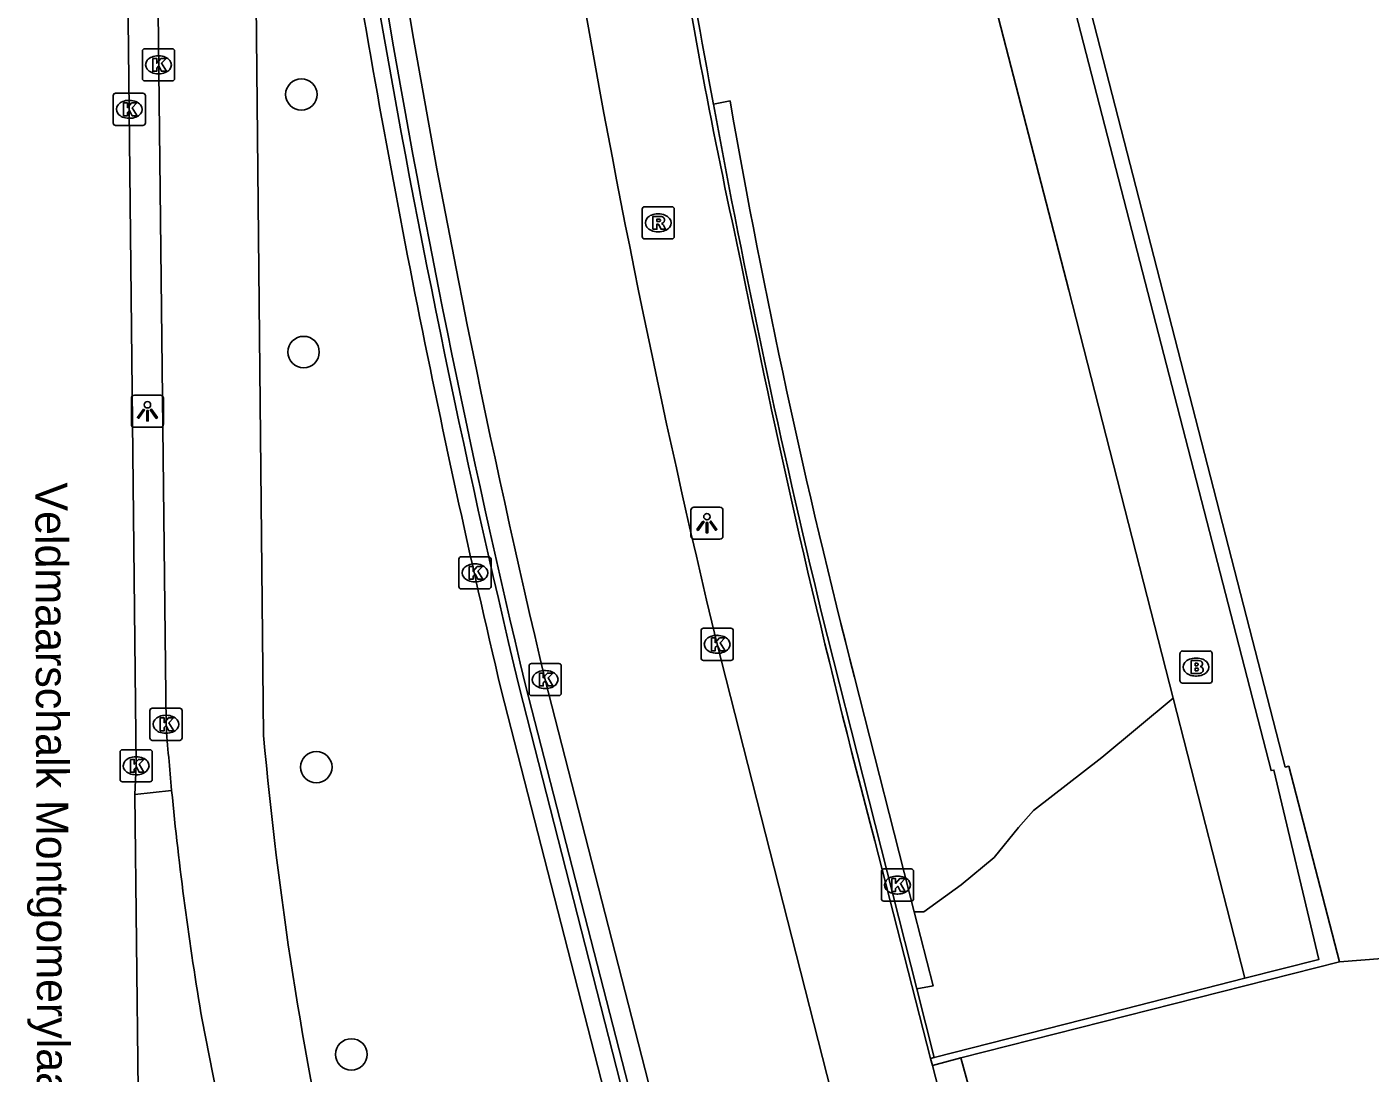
# Model space of a CAD drawing. Extents: x 160806 to 161707, y 383697 to 384148.
# Drawn here: x 161237.99 to 161279.79, y 383960.49 to 383993.06 of the extents above; entities that cross this region are included whole.
import ezdxf

# ---------------------------------------------------------------- set-up
doc = ezdxf.new("R2010")
doc.units = 0
for name, color, linetype in [('IMGEO_Boom', 7, 'Continuous'), ('IMGEO_Brandkraan', 7, 'Continuous'), ('IMGEO_Fietspad_open', 7, 'Continuous'), ('IMGEO_Groenvoorziening', 7, 'Continuous'), ('IMGEO_Kolk', 7, 'Continuous'), ('IMGEO_Lichtpunt', 7, 'Continuous'), ('IMGEO_Muur', 7, 'Continuous'), ('IMGEO_Openbare_ruimte_label', 7, 'Continuous'), ('IMGEO_Rijbaan_lokaal_gesloten', 7, 'Continuous'), ('IMGEO_Rioolput', 7, 'Continuous'), ('IMGEO_Verkeerseiland_gesloten', 7, 'Continuous'), ('IMGEO_Verkeerseiland_open', 7, 'Continuous'), ('IMGEO_Voetpad_gesloten', 7, 'Continuous'), ('IMGEO_Voetpad_open', 7, 'Continuous')]:
    doc.layers.add(name, color=color, linetype=linetype)

msp = doc.modelspace()

# ---------------------------------------------------------------- linework, layer by layer
at = {"layer": 'IMGEO_Boom'}
for centre in [(161246.528, 383990.956), (161246.596, 383982.939), (161246.992, 383970.018), (161248.083, 383961.076)]:
    msp.add_circle(centre, 0.489, dxfattribs=at)
at = {"layer": 'IMGEO_Brandkraan'}
for p, q in [((161273.87, 383972.707), (161273.87, 383973.559)), ((161273.945, 383973.633), (161274.797, 383973.633)), ((161274.358, 383973.413), (161274.383, 383973.413)), ((161274.871, 383973.559), (161274.871, 383972.707)), ((161274.797, 383972.633), (161273.945, 383972.633)), ((161274.381, 383972.853), (161274.356, 383972.853))]:
    msp.add_line(p, q, dxfattribs=at)
for points in [[(161273.87, 383972.707), (161273.87, 383973.559)], [(161273.945, 383973.633), (161274.797, 383973.633)], [(161274.218, 383973.333), (161274.218, 383972.933), (161274.431, 383972.933)], [(161274.449, 383973.333), (161274.218, 383973.333)], [(161274.871, 383973.559), (161274.871, 383972.707)], [(161274.397, 383973.252), (161274.343, 383973.252), (161274.343, 383973.176)], [(161274.343, 383973.176), (161274.396, 383973.176)], [(161274.405, 383973.1), (161274.343, 383973.1), (161274.343, 383973.019)], [(161274.343, 383973.019), (161274.405, 383973.019)], [(161274.797, 383972.633), (161273.945, 383972.633)]]:
    msp.add_lwpolyline(points, dxfattribs=at)
for centre, radius, start, end in [((161273.947, 383973.557), 0.0765, 91.552, 178.448), ((161273.947, 383973.557), 0.0765, 91.552, 178.448), ((161274.453, 383973.188), 0.145, 59.4692, 91.5367), ((161274.478, 383973.235), 0.0922, 285.5137, 58.1501), ((161274.795, 383973.557), 0.0765, 1.552, 88.448), ((161274.795, 383973.557), 0.0765, 1.552, 88.448), ((161274.398, 383973.214), 0.0379, 267.8285, 90.9355), ((161274.406, 383973.059), 0.0404, 269.8759, 90.5077), ((161274.437, 383973.184), 0.251, 268.6676, 293.5347), ((161274.483, 383973.043), 0.105, 301.3115, 78.989), ((161273.947, 383972.709), 0.0765, 181.552, 268.448), ((161273.947, 383972.709), 0.0765, 181.552, 268.448), ((161274.795, 383972.709), 0.0765, 271.552, 358.448), ((161274.795, 383972.709), 0.0765, 271.552, 358.448)]:
    msp.add_arc(centre, radius, start, end, dxfattribs=at)
for centre, major_axis, ratio, start_param, end_param in [((161274.357, 383973.133), (-0.387, 0.002), 0.722429, 4.712389, 7.853982), ((161274.382, 383973.133), (-0.39, 0.002), 0.717154, 1.570796, 4.712389)]:
    msp.add_ellipse(centre, major_axis=major_axis, ratio=ratio, start_param=start_param, end_param=end_param, dxfattribs=at)
at = {"layer": 'IMGEO_Fietspad_open'}
for points in [[(161241.737, 384044.23), (161241.861, 384012.393), (161241.998, 384000), (161242.316, 383971.348)], [(161245.354, 383970.999), (161245.058, 384000), (161244.731, 384032.028), (161244.792, 384040.216)], [(161266.435, 383946.5), (161265.897, 383948.588), (161264.804, 383952.922), (161259.465, 383973.845)], [(161261.187, 383945.139), (161260.855, 383946.434), (161254.116, 383972.74)], [(161246.739, 383948.007), (161244.797, 383955.231), (161243.442, 383962.149)]]:
    msp.add_lwpolyline(points, dxfattribs=at)
for centre, radius, start, end in [((161578.56, 384050.467), 328.165, 189.56836, 193.5024), ((161576.726, 384049.366), 331.586, 189.45347, 193.3612), ((161338.146, 383978.483), 96.095, 184.25791, 185.48645), ((161357.327, 383980.918), 112.412, 185.06229, 192.69832), ((161341.239, 383978.8), 99.205, 185.49822, 189.66271)]:
    msp.add_arc(centre, radius, start, end, dxfattribs=at)
at = {"layer": 'IMGEO_Groenvoorziening'}
msp.add_lwpolyline([(161273.656, 383972.166), (161271.438, 383970.317), (161269.309, 383968.667), (161268.844, 383968.144), (161268.086, 383967.207), (161267.06, 383966.359), (161265.9, 383965.512), (161265.599, 383965.509)], dxfattribs=at)
at = {"layer": 'IMGEO_Kolk'}
for p, q in [((161241.581, 383991.454), (161241.581, 383992.306)), ((161241.656, 383992.38), (161242.508, 383992.38)), ((161242.069, 383992.16), (161242.094, 383992.16)), ((161242.582, 383992.306), (161242.582, 383991.454)), ((161242.508, 383991.38), (161241.656, 383991.38)), ((161242.092, 383991.6), (161242.067, 383991.6)), ((161240.672, 383990.068), (161240.672, 383990.92)), ((161240.747, 383990.994), (161241.599, 383990.994)), ((161241.673, 383990.92), (161241.673, 383990.068)), ((161241.16, 383990.774), (161241.185, 383990.774)), ((161241.183, 383990.214), (161241.158, 383990.214)), ((161241.599, 383989.994), (161240.747, 383989.994)), ((161251.429, 383975.64), (161251.429, 383976.492)), ((161251.504, 383976.566), (161252.356, 383976.566)), ((161251.917, 383976.346), (161251.942, 383976.346)), ((161252.43, 383976.492), (161252.43, 383975.64)), ((161252.356, 383975.566), (161251.504, 383975.566)), ((161251.94, 383975.786), (161251.915, 383975.786)), ((161258.966, 383973.415), (161258.966, 383974.267)), ((161259.041, 383974.341), (161259.893, 383974.341)), ((161259.967, 383974.267), (161259.967, 383973.415)), ((161259.454, 383974.121), (161259.479, 383974.121)), ((161259.893, 383973.341), (161259.041, 383973.341)), ((161259.477, 383973.561), (161259.452, 383973.561)), ((161253.613, 383972.318), (161253.613, 383973.17)), ((161253.688, 383973.244), (161254.54, 383973.244)), ((161254.101, 383973.024), (161254.126, 383973.024)), ((161254.614, 383973.17), (161254.614, 383972.318)), ((161254.124, 383972.464), (161254.099, 383972.464)), ((161254.54, 383972.244), (161253.688, 383972.244)), ((161241.814, 383970.926), (161241.814, 383971.778)), ((161241.889, 383971.852), (161242.741, 383971.852)), ((161242.302, 383971.632), (161242.327, 383971.632)), ((161242.815, 383971.778), (161242.815, 383970.926)), ((161242.741, 383970.852), (161241.889, 383970.852)), ((161242.325, 383971.072), (161242.3, 383971.072)), ((161240.885, 383969.635), (161240.885, 383970.487)), ((161240.96, 383970.561), (161241.812, 383970.561)), ((161241.886, 383970.487), (161241.886, 383969.635)), ((161241.373, 383970.341), (161241.398, 383970.341)), ((161241.812, 383969.561), (161240.96, 383969.561)), ((161241.396, 383969.781), (161241.371, 383969.781)), ((161264.577, 383965.922), (161264.577, 383966.774)), ((161264.652, 383966.848), (161265.504, 383966.848)), ((161265.065, 383966.628), (161265.09, 383966.628)), ((161265.578, 383966.774), (161265.578, 383965.922)), ((161265.504, 383965.848), (161264.652, 383965.848)), ((161265.088, 383966.068), (161265.063, 383966.068))]:
    msp.add_line(p, q, dxfattribs=at)
for points in [[(161241.581, 383991.454), (161241.581, 383992.306)], [(161241.656, 383992.38), (161242.508, 383992.38)], [(161242.582, 383992.306), (161242.582, 383991.454)], [(161241.902, 383992.08), (161242.025, 383992.08), (161242.025, 383991.929), (161242.155, 383992.08), (161242.319, 383992.08), (161242.173, 383991.929), (161242.326, 383991.68), (161242.174, 383991.68), (161242.089, 383991.844), (161242.025, 383991.777), (161242.025, 383991.68), (161241.902, 383991.68), (161241.902, 383992.08)], [(161242.508, 383991.38), (161241.656, 383991.38)], [(161240.672, 383990.068), (161240.672, 383990.92)], [(161240.747, 383990.994), (161241.599, 383990.994)], [(161241.673, 383990.92), (161241.673, 383990.068)], [(161240.993, 383990.694), (161241.116, 383990.694), (161241.116, 383990.543), (161241.246, 383990.694), (161241.41, 383990.694), (161241.264, 383990.543), (161241.417, 383990.294), (161241.265, 383990.294), (161241.18, 383990.458), (161241.116, 383990.391), (161241.116, 383990.294), (161240.993, 383990.294), (161240.993, 383990.694)], [(161241.599, 383989.994), (161240.747, 383989.994)], [(161251.429, 383975.64), (161251.429, 383976.492)], [(161251.504, 383976.566), (161252.356, 383976.566)], [(161251.75, 383976.266), (161251.873, 383976.266), (161251.873, 383976.115), (161252.003, 383976.266), (161252.167, 383976.266), (161252.021, 383976.115), (161252.174, 383975.866), (161252.022, 383975.866), (161251.937, 383976.03), (161251.873, 383975.963), (161251.873, 383975.866), (161251.75, 383975.866), (161251.75, 383976.266)], [(161252.43, 383976.492), (161252.43, 383975.64)], [(161252.356, 383975.566), (161251.504, 383975.566)], [(161258.966, 383973.415), (161258.966, 383974.267)], [(161259.041, 383974.341), (161259.893, 383974.341)], [(161259.967, 383974.267), (161259.967, 383973.415)], [(161259.287, 383974.041), (161259.41, 383974.041), (161259.41, 383973.89), (161259.54, 383974.041), (161259.704, 383974.041), (161259.558, 383973.89), (161259.711, 383973.641), (161259.559, 383973.641), (161259.474, 383973.805), (161259.41, 383973.738), (161259.41, 383973.641), (161259.287, 383973.641), (161259.287, 383974.041)], [(161259.893, 383973.341), (161259.041, 383973.341)], [(161253.613, 383972.318), (161253.613, 383973.17)], [(161253.688, 383973.244), (161254.54, 383973.244)], [(161253.934, 383972.944), (161254.057, 383972.944), (161254.057, 383972.793), (161254.187, 383972.944), (161254.351, 383972.944), (161254.205, 383972.793), (161254.358, 383972.544), (161254.206, 383972.544), (161254.121, 383972.708), (161254.057, 383972.641), (161254.057, 383972.544), (161253.934, 383972.544), (161253.934, 383972.944)], [(161254.614, 383973.17), (161254.614, 383972.318)], [(161254.54, 383972.244), (161253.688, 383972.244)], [(161241.814, 383970.926), (161241.814, 383971.778)], [(161241.889, 383971.852), (161242.741, 383971.852)], [(161242.815, 383971.778), (161242.815, 383970.926)], [(161242.135, 383971.552), (161242.258, 383971.552), (161242.258, 383971.401), (161242.388, 383971.552), (161242.552, 383971.552), (161242.406, 383971.401), (161242.559, 383971.152), (161242.407, 383971.152), (161242.322, 383971.316), (161242.258, 383971.249), (161242.258, 383971.152), (161242.135, 383971.152), (161242.135, 383971.552)], [(161242.741, 383970.852), (161241.889, 383970.852)], [(161240.885, 383969.635), (161240.885, 383970.487)], [(161240.96, 383970.561), (161241.812, 383970.561)], [(161241.886, 383970.487), (161241.886, 383969.635)], [(161241.206, 383970.261), (161241.329, 383970.261), (161241.329, 383970.11), (161241.459, 383970.261), (161241.623, 383970.261), (161241.477, 383970.11), (161241.63, 383969.861), (161241.478, 383969.861), (161241.393, 383970.025), (161241.329, 383969.958), (161241.329, 383969.861), (161241.206, 383969.861), (161241.206, 383970.261)], [(161241.812, 383969.561), (161240.96, 383969.561)], [(161264.577, 383965.922), (161264.577, 383966.774)], [(161264.652, 383966.848), (161265.504, 383966.848)], [(161265.578, 383966.774), (161265.578, 383965.922)], [(161264.898, 383966.548), (161265.021, 383966.548), (161265.021, 383966.397), (161265.151, 383966.548), (161265.315, 383966.548), (161265.169, 383966.397), (161265.322, 383966.148), (161265.17, 383966.148), (161265.085, 383966.312), (161265.021, 383966.245), (161265.021, 383966.148), (161264.898, 383966.148), (161264.898, 383966.548)], [(161265.504, 383965.848), (161264.652, 383965.848)]]:
    msp.add_lwpolyline(points, dxfattribs=at)
for centre, start, end in [((161241.658, 383992.304), 91.552, 178.448), ((161241.658, 383992.304), 91.552, 178.448), ((161242.506, 383992.304), 1.552, 88.448), ((161242.506, 383992.304), 1.552, 88.448), ((161241.658, 383991.456), 181.552, 268.448), ((161241.658, 383991.456), 181.552, 268.448), ((161242.506, 383991.456), 271.552, 358.448), ((161242.506, 383991.456), 271.552, 358.448), ((161240.749, 383990.918), 91.552, 178.448), ((161240.749, 383990.918), 91.552, 178.448), ((161241.597, 383990.918), 1.552, 88.448), ((161241.597, 383990.918), 1.552, 88.448), ((161240.749, 383990.07), 181.552, 268.448), ((161240.749, 383990.07), 181.552, 268.448), ((161241.597, 383990.07), 271.552, 358.448), ((161241.597, 383990.07), 271.552, 358.448), ((161251.506, 383976.49), 91.552, 178.448), ((161251.506, 383976.49), 91.552, 178.448), ((161252.354, 383976.49), 1.552, 88.448), ((161252.354, 383976.49), 1.552, 88.448), ((161251.506, 383975.642), 181.552, 268.448), ((161251.506, 383975.642), 181.552, 268.448), ((161252.354, 383975.642), 271.552, 358.448), ((161252.354, 383975.642), 271.552, 358.448), ((161259.043, 383974.265), 91.552, 178.448), ((161259.043, 383974.265), 91.552, 178.448), ((161259.891, 383974.265), 1.552, 88.448), ((161259.891, 383974.265), 1.552, 88.448), ((161259.043, 383973.417), 181.552, 268.448), ((161259.043, 383973.417), 181.552, 268.448), ((161259.891, 383973.417), 271.552, 358.448), ((161259.891, 383973.417), 271.552, 358.448), ((161253.69, 383973.168), 91.552, 178.448), ((161253.69, 383973.168), 91.552, 178.448), ((161254.538, 383973.168), 1.552, 88.448), ((161254.538, 383973.168), 1.552, 88.448), ((161253.69, 383972.32), 181.552, 268.448), ((161253.69, 383972.32), 181.552, 268.448), ((161254.538, 383972.32), 271.552, 358.448), ((161254.538, 383972.32), 271.552, 358.448), ((161241.891, 383971.776), 91.552, 178.448), ((161241.891, 383971.776), 91.552, 178.448), ((161242.739, 383971.776), 1.552, 88.448), ((161242.739, 383971.776), 1.552, 88.448), ((161241.891, 383970.928), 181.552, 268.448), ((161241.891, 383970.928), 181.552, 268.448), ((161242.739, 383970.928), 271.552, 358.448), ((161242.739, 383970.928), 271.552, 358.448), ((161240.962, 383970.485), 91.552, 178.448), ((161240.962, 383970.485), 91.552, 178.448), ((161241.81, 383970.485), 1.552, 88.448), ((161241.81, 383970.485), 1.552, 88.448), ((161240.962, 383969.637), 181.552, 268.448), ((161240.962, 383969.637), 181.552, 268.448), ((161241.81, 383969.637), 271.552, 358.448), ((161241.81, 383969.637), 271.552, 358.448), ((161264.654, 383966.772), 91.552, 178.448), ((161264.654, 383966.772), 91.552, 178.448), ((161265.502, 383966.772), 1.552, 88.448), ((161265.502, 383966.772), 1.552, 88.448), ((161264.654, 383965.924), 181.552, 268.448), ((161264.654, 383965.924), 181.552, 268.448), ((161265.502, 383965.924), 271.552, 358.448), ((161265.502, 383965.924), 271.552, 358.448)]:
    msp.add_arc(centre, 0.0765, start, end, dxfattribs=at)
for centre, major_axis, ratio, start_param, end_param in [((161242.068, 383991.88), (-0.387, 0.002), 0.722429, 4.712389, 7.853982), ((161242.093, 383991.88), (-0.39, 0.002), 0.717154, 1.570796, 4.712389), ((161241.159, 383990.494), (-0.387, 0.002), 0.722429, 4.712389, 7.853982), ((161241.184, 383990.494), (-0.39, 0.002), 0.717154, 1.570796, 4.712389), ((161251.916, 383976.066), (-0.387, 0.002), 0.722429, 4.712389, 7.853982), ((161251.941, 383976.066), (-0.39, 0.002), 0.717154, 1.570796, 4.712389), ((161259.453, 383973.841), (-0.387, 0.002), 0.722429, 4.712389, 7.853982), ((161259.478, 383973.841), (-0.39, 0.002), 0.717154, 1.570796, 4.712389), ((161254.1, 383972.744), (-0.387, 0.002), 0.722429, 4.712389, 7.853982), ((161254.125, 383972.744), (-0.39, 0.002), 0.717154, 1.570796, 4.712389), ((161242.301, 383971.352), (-0.387, 0.002), 0.722429, 4.712389, 7.853982), ((161242.326, 383971.352), (-0.39, 0.002), 0.717154, 1.570796, 4.712389), ((161241.372, 383970.061), (-0.387, 0.002), 0.722429, 4.712389, 7.853982), ((161241.397, 383970.061), (-0.39, 0.002), 0.717154, 1.570796, 4.712389), ((161265.064, 383966.348), (-0.387, 0.002), 0.722429, 4.712389, 7.853982), ((161265.089, 383966.348), (-0.39, 0.002), 0.717154, 1.570796, 4.712389)]:
    msp.add_ellipse(centre, major_axis=major_axis, ratio=ratio, start_param=start_param, end_param=end_param, dxfattribs=at)
at = {"layer": 'IMGEO_Lichtpunt'}
for p, q in [((161241.238, 383981.5), (161241.238, 383980.693)), ((161241.238, 383981.5), (161241.238, 383980.693)), ((161242.14, 383981.595), (161241.332, 383981.595)), ((161242.14, 383981.595), (161241.332, 383981.595)), ((161242.234, 383980.693), (161242.234, 383981.5)), ((161242.234, 383980.693), (161242.234, 383981.5)), ((161241.332, 383980.599), (161242.14, 383980.599)), ((161241.332, 383980.599), (161242.14, 383980.599)), ((161258.65, 383978.015), (161258.65, 383977.208)), ((161258.65, 383978.015), (161258.65, 383977.208)), ((161259.552, 383978.11), (161258.744, 383978.11)), ((161259.552, 383978.11), (161258.744, 383978.11)), ((161259.646, 383977.208), (161259.646, 383978.015)), ((161259.646, 383977.208), (161259.646, 383978.015)), ((161258.744, 383977.114), (161259.552, 383977.114)), ((161258.744, 383977.114), (161259.552, 383977.114))]:
    msp.add_line(p, q, dxfattribs=at)
for points in [[(161241.612, 383981.164), (161241.651, 383981.136), (161241.463, 383980.874), (161241.425, 383980.901), (161241.612, 383981.164)], [(161241.714, 383981.116), (161241.761, 383981.116), (161241.761, 383980.794), (161241.714, 383980.794), (161241.714, 383981.116)], [(161241.824, 383981.136), (161241.862, 383981.163), (161242.049, 383980.901), (161242.01, 383980.873), (161241.824, 383981.136)], [(161259.024, 383977.679), (161259.063, 383977.651), (161258.875, 383977.389), (161258.837, 383977.416), (161259.024, 383977.679)], [(161259.126, 383977.631), (161259.173, 383977.631), (161259.173, 383977.309), (161259.126, 383977.309), (161259.126, 383977.631)], [(161259.236, 383977.651), (161259.274, 383977.678), (161259.461, 383977.416), (161259.422, 383977.388), (161259.236, 383977.651)]]:
    msp.add_lwpolyline(points, dxfattribs=at)
for centre in [(161241.737, 383981.298), (161259.149, 383977.813)]:
    msp.add_circle(centre, 0.0994, dxfattribs=at)
for centre, start, end in [((161241.332, 383981.5), 90, 180), ((161241.332, 383981.5), 90, 180), ((161242.14, 383981.5), 0, 90), ((161242.14, 383981.5), 0, 90), ((161241.332, 383980.693), 180, 270), ((161241.332, 383980.693), 180, 270), ((161242.14, 383980.693), 270, 0), ((161242.14, 383980.693), 270, 360), ((161258.744, 383978.015), 90, 180), ((161258.744, 383978.015), 90, 180), ((161259.552, 383978.015), 0, 90), ((161259.552, 383978.015), 0, 90), ((161258.744, 383977.208), 180, 270), ((161258.744, 383977.208), 180, 270), ((161259.552, 383977.208), 270, 0), ((161259.552, 383977.208), 270, 360)]:
    msp.add_arc(centre, 0.0946, start, end, dxfattribs=at)
at = {"layer": 'IMGEO_Muur'}
for points in [[(161275.884, 383963.446), (161278.191, 383964.035), (161276.791, 383969.927), (161276.705, 383969.909), (161268.946, 384000), (161255.62, 384051.677), (161254.903, 384055.513)], [(161255.944, 384052.5), (161269.44, 384000), (161277.147, 383970.021), (161277.255, 383970.048), (161278.831, 383963.961)], [(161262.717, 383974.82), (161265.682, 383963.113)], [(161260.405, 383944.467), (161260.252, 383944.428), (161257.82, 383953.975), (161258.021, 383954.036), (161253.305, 383972.52)], [(161253.505, 383972.568), (161260.591, 383944.984)], [(161264.37, 383967.723), (161266.11, 383960.95)], [(161278.831, 383963.961), (161267.055, 383960.972)], [(161266.225, 383960.979), (161270.865, 383962.164), (161275.884, 383963.446)], [(161265.682, 383963.113), (161266.225, 383960.979)], [(161266.11, 383960.95), (161266.225, 383960.979)], [(161266.166, 383960.733), (161266.11, 383960.95)], [(161267.055, 383960.972), (161266.166, 383960.733)]]:
    msp.add_lwpolyline(points, dxfattribs=at)
for centre, radius, start, end in [((161495.296, 384035.145), 240.101, 187.72845, 190.67976), ((161467.348, 384031.159), 212.062, 189.33099, 192.39502), ((161584.143, 384051.855), 340.218, 189.68245, 193.48495), ((161571.567, 384048.687), 327.044, 189.5132, 193.45897), ((161545.736, 384043.218), 291.166, 190.40139, 193.58635), ((161554.196, 384044.145), 299.732, 191.25587, 194.77166)]:
    msp.add_arc(centre, radius, start, end, dxfattribs=at)
at = {"layer": 'IMGEO_Rijbaan_lokaal_gesloten'}
for points in [[(161241.35, 383969.171), (161241.386, 383970.061), (161241.173, 383990.494), (161240.939, 384010.954), (161240.824, 384032.428), (161240.812, 384047.358), (161240.812, 384047.879)], [(161241.503, 383955.344), (161241.35, 383969.171)]]:
    msp.add_lwpolyline(points, dxfattribs=at)
at = {"layer": 'IMGEO_Rioolput'}
for p, q in [((161257.132, 383986.535), (161257.132, 383987.387)), ((161257.207, 383987.461), (161258.059, 383987.461)), ((161257.62, 383987.241), (161257.645, 383987.241)), ((161258.133, 383987.387), (161258.133, 383986.535)), ((161257.643, 383986.681), (161257.618, 383986.681)), ((161258.059, 383986.461), (161257.207, 383986.461))]:
    msp.add_line(p, q, dxfattribs=at)
for points in [[(161257.132, 383986.535), (161257.132, 383987.387)], [(161257.207, 383987.461), (161258.059, 383987.461)], [(161257.721, 383987.159), (161257.469, 383987.161), (161257.469, 383986.761)], [(161258.133, 383987.387), (161258.133, 383986.535)], [(161257.469, 383986.761), (161257.593, 383986.761), (161257.593, 383986.923), (161257.604, 383986.923)], [(161257.647, 383987.08), (161257.593, 383987.08), (161257.593, 383986.999)], [(161257.593, 383986.999), (161257.645, 383986.999)], [(161257.651, 383986.894), (161257.722, 383986.761), (161257.862, 383986.761), (161257.797, 383986.887)], [(161258.059, 383986.461), (161257.207, 383986.461)]]:
    msp.add_lwpolyline(points, dxfattribs=at)
for centre, radius, start, end in [((161257.209, 383987.385), 0.0765, 91.552, 178.448), ((161257.209, 383987.385), 0.0765, 91.552, 178.448), ((161257.72, 383987.049), 0.109, 350.3612, 89.416), ((161258.057, 383987.385), 0.0765, 1.552, 88.448), ((161258.057, 383987.385), 0.0765, 1.552, 88.448), ((161257.603, 383986.87), 0.0533, 26.0293, 88.6989), ((161257.629, 383987.188), 0.19, 274.7715, 282.9687), ((161257.653, 383986.984), 0.0964, 77.0061, 93.1865), ((161257.667, 383987.041), 0.0378, 276.6634, 79.6772), ((161257.718, 383987.049), 0.112, 277.5842, 350.9817), ((161257.702, 383986.834), 0.108, 29.5134, 73.7905), ((161257.209, 383986.537), 0.0765, 181.552, 268.448), ((161257.209, 383986.537), 0.0765, 181.552, 268.448), ((161258.057, 383986.537), 0.0765, 271.552, 358.448), ((161258.057, 383986.537), 0.0765, 271.552, 358.448)]:
    msp.add_arc(centre, radius, start, end, dxfattribs=at)
for centre, major_axis, ratio, start_param, end_param in [((161257.619, 383986.961), (-0.387, 0.002), 0.722429, 4.712389, 7.853982), ((161257.644, 383986.961), (-0.39, 0.002), 0.717154, 1.570796, 4.712389)]:
    msp.add_ellipse(centre, major_axis=major_axis, ratio=ratio, start_param=start_param, end_param=end_param, dxfattribs=at)
at = {"layer": 'IMGEO_Verkeerseiland_gesloten'}
msp.add_lwpolyline([(161242.491, 383969.295), (161241.35, 383969.171)], dxfattribs=at)
at = {"layer": 'IMGEO_Verkeerseiland_open'}
msp.add_lwpolyline([(161252.747, 383972.429), (161259.999, 383944.142), (161260.464, 383944.229)], dxfattribs=at)
msp.add_arc((161585.132, 384051.153), 341.581, 189.08772, 193.32481, dxfattribs=at)
at = {"layer": 'IMGEO_Voetpad_gesloten'}
for points in [[(161278.831, 383963.961), (161284.147, 383964.369), (161284.463, 383960.399)], [(161268.056, 383957.312), (161267.055, 383960.972)], [(161266.166, 383960.733), (161267.108, 383957.061)]]:
    msp.add_lwpolyline(points, dxfattribs=at)
at = {"layer": 'IMGEO_Voetpad_open'}
for points in [[(161273.656, 383972.166), (161270.413, 383984.864), (161266.498, 384000), (161265.158, 384005.179)], [(161259.867, 383990.754), (161259.354, 383990.65)], [(161265.599, 383965.509), (161263.74, 383972.819)], [(161275.884, 383963.446), (161273.656, 383972.166)], [(161265.599, 383965.509), (161266.184, 383963.21), (161265.682, 383963.113)]]:
    msp.add_lwpolyline(points, dxfattribs=at)
msp.add_arc((161492.705, 384031.649), 236.402, 189.96163, 194.40977, dxfattribs=at)

# ---------------------------------------------------------------- texts
at = {"layer": 'IMGEO_Openbare_ruimte_label'}
msp.add_text('Veldmaarschalk Montgomerylaan', height=1, rotation=270.1719, dxfattribs=at).set_placement((161238.248, 383978.88))

doc.saveas('drawing.dxf')
